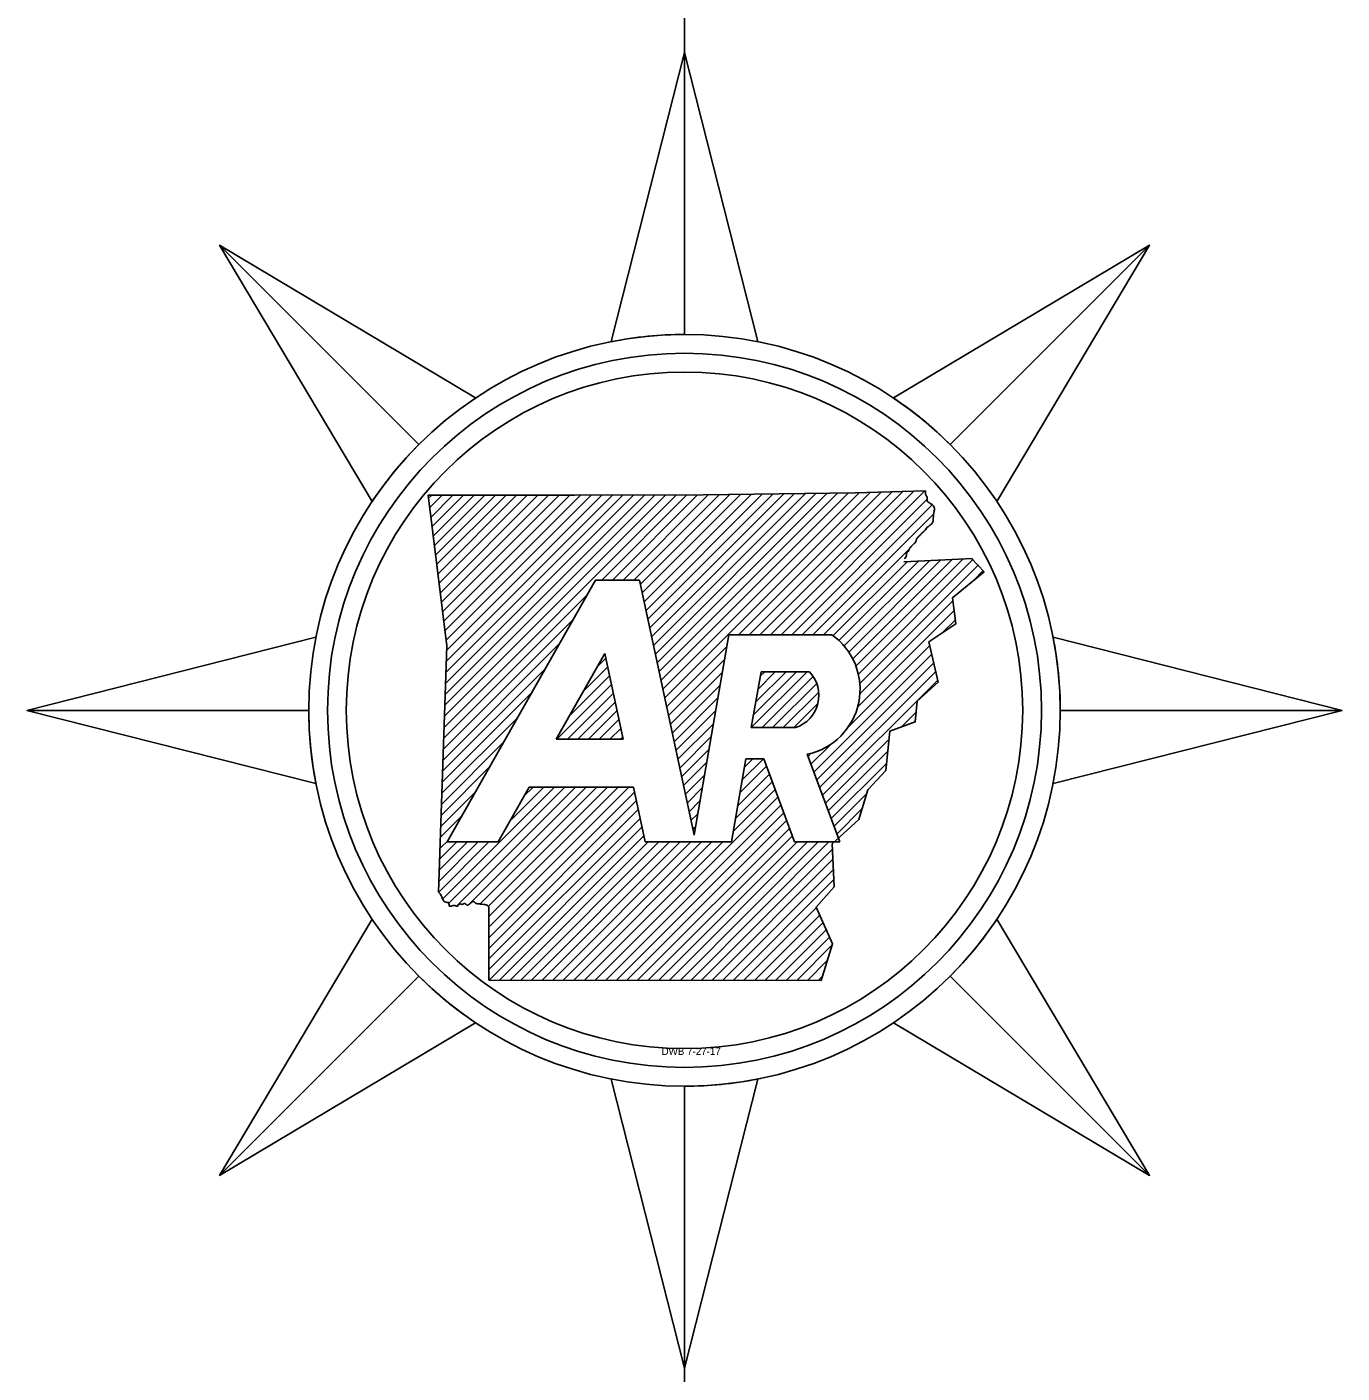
# Model space of a CAD drawing. Extents: x 6028666 to 6031787, y 5366484 to 5368484.
# Drawn here: x 6030749.6 to 6030875, y 5366874.2 to 5367002.5 of the extents above; entities that cross this region are included whole.
import ezdxf

# ---------------------------------------------------------------- set-up
doc = ezdxf.new("R2010")
doc.units = 0
doc.layers.add('R_Draft', color=7, linetype='Continuous')
doc.layers.add('R_Water Annot', color=7, linetype='Continuous')

msp = doc.modelspace()

# ---------------------------------------------------------------- linework, layer by layer
at = {"layer": 'R_Draft'}
for p, q in [((6030812.31, 5367118.56), (6030812.31, 5366977.1)), ((6030812.31, 5367000.07), (6030805.33, 5366972.51)), ((6030812.31, 5366973.19), (6030812.31, 5367000.07)), ((6030767.97, 5366981.7), (6030786.97, 5366962.7)), ((6030786.97, 5366962.7), (6030767.97, 5366981.7)), ((6030767.97, 5366981.7), (6030782.52, 5366957.28)), ((6030856.65, 5366981.7), (6030832.23, 5366967.15)), ((6030837.65, 5366962.7), (6030856.65, 5366981.7)), ((6030837.65, 5366962.7), (6030856.65, 5366981.7)), ((6030789.68, 5366924.81), (6030803.82, 5366949.78)), ((6030803.82, 5366949.78), (6030808.02, 5366949.78)), ((6030816.55, 5366944.57), (6030826.36, 5366944.57)), ((6030875.01, 5366937.36), (6030847.45, 5366944.34)), ((6030800.08, 5366934.61), (6030804.7, 5366942.77)), ((6030819.61, 5366941.04), (6030824.22, 5366941.04)), ((6030749.6, 5366937.36), (6030776.48, 5366937.36)), ((6030776.48, 5366937.36), (6030749.6, 5366937.36)), ((6030749.6, 5366937.36), (6030777.16, 5366930.38)), ((6030848.14, 5366937.36), (6030875.01, 5366937.36)), ((6030848.14, 5366937.36), (6030875.01, 5366937.36)), ((6030818.68, 5366935.71), (6030822.89, 5366935.71)), ((6030800.08, 5366934.61), (6030806.45, 5366934.61)), ((6030819.86, 5366932.75), (6030818.16, 5366932.75)), ((6030822.79, 5366924.81), (6030819.86, 5366932.75)), ((6030824.02, 5366933.17), (6030827.11, 5366924.81)), ((6030797.5, 5366930.05), (6030794.53, 5366924.81)), ((6030807.43, 5366930.05), (6030797.5, 5366930.05)), ((6030794.53, 5366924.81), (6030789.68, 5366924.81)), ((6030816.78, 5366924.81), (6030808.55, 5366924.81)), ((6030827.11, 5366924.81), (6030822.79, 5366924.81)), ((6030856.65, 5366893.02), (6030842.09, 5366917.44)), ((6030767.97, 5366893.02), (6030786.97, 5366912.02)), ((6030786.97, 5366912.02), (6030767.97, 5366893.02)), ((6030837.65, 5366912.02), (6030856.65, 5366893.02)), ((6030837.65, 5366912.02), (6030856.65, 5366893.02)), ((6030767.97, 5366893.02), (6030792.39, 5366907.57)), ((6030812.31, 5366874.65), (6030819.29, 5366902.21)), ((6030812.31, 5366901.53), (6030812.31, 5366901.53)), ((6030812.31, 5366901.53), (6030812.31, 5366786.82)), ((6030812.31, 5366901.53), (6030812.31, 5366874.65))]:
    msp.add_line(p, q, dxfattribs=at)
for points in [[(6030805.33, 5366972.51), (6030812.31, 5367000.07), (6030819.29, 5366972.51)], [(6030782.52, 5366957.28), (6030767.97, 5366981.7), (6030792.39, 5366967.15)], [(6030832.23, 5366967.15), (6030856.65, 5366981.7), (6030842.09, 5366957.28)], [(6030787.85, 5366957.87), (6030801.83, 5366957.86), (6030814.1, 5366957.89), (6030828.57, 5366958.11), (6030835.28, 5366958.27)], [(6030788.86, 5366920.04), (6030789.64, 5366943.5), (6030787.85, 5366957.87)], [(6030839.67, 5366951.85), (6030840.88, 5366950.58), (6030837.87, 5366948.1), (6030838.19, 5366945.6), (6030835.61, 5366943.89), (6030836.49, 5366940.04), (6030834.5, 5366938.22), (6030834.32, 5366936.25), (6030831.89, 5366935.37), (6030831.52, 5366931.64), (6030829.78, 5366929.78), (6030828.93, 5366926.96), (6030826.4, 5366924.64), (6030826.59, 5366920.54), (6030824.86, 5366918.61), (6030826.43, 5366915.1), (6030825.35, 5366911.6)], [(6030833.21, 5366951.52), (6030839.77, 5366951.85)], [(6030808.02, 5366949.78), (6030813.22, 5366925.48), (6030816.55, 5366944.57)], [(6030777.16, 5366930.38), (6030749.6, 5366937.36), (6030777.16, 5366944.34)], [(6030847.45, 5366944.34), (6030875.01, 5366937.36), (6030847.45, 5366930.38)], [(6030804.7, 5366942.77), (6030806.45, 5366934.61)], [(6030818.68, 5366935.71), (6030819.61, 5366941.04)], [(6030818.16, 5366932.75), (6030816.78, 5366924.81)], [(6030808.55, 5366924.81), (6030807.43, 5366930.05)], [(6030825.35, 5366911.6), (6030793.66, 5366911.65), (6030793.64, 5366918.65)], [(6030792.39, 5366907.57), (6030767.97, 5366893.02), (6030782.52, 5366917.44)], [(6030842.09, 5366917.44), (6030856.65, 5366893.02), (6030832.23, 5366907.57)], [(6030819.29, 5366902.21), (6030812.31, 5366874.65), (6030805.33, 5366902.21)]]:
    msp.add_lwpolyline(points, dxfattribs=at)
for radius in [35.83, 32.25]:
    msp.add_circle((6030812.31, 5366937.36), radius, dxfattribs=at)
for centre, radius, start, end in [((6030812.31, 5366937.36), 35.83, 90, 101.2291), ((6030812.31, 5366937.36), 35.83, 45, 56.2291), ((6030812.31, 5366937.36), 35.83, 135, 146.2291), ((6030822.71, 5366939.38), 6.34, 281.8626, 54.8705), ((6030812.31, 5366937.36), 35.83, 0, 11.2291), ((6030821.88, 5366938.79), 3.24, 288.1268, 43.8902), ((6030812.31, 5366937.36), 35.83, 180, 191.2291), ((6030812.31, 5366937.36), 35.83, 315, 326.2291), ((6030812.31, 5366937.36), 35.83, 225, 236.2291), ((6030812.31, 5366937.36), 35.83, 270, 281.2291)]:
    msp.add_arc(centre, radius, start, end, dxfattribs=at)
for points in [[(6030835.28, 5366958.27), (6030835.33, 5366957.89), (6030835.45, 5366957.69), (6030835.46, 5366957.33), (6030835.61, 5366957.17), (6030835.86, 5366957.02), (6030836.09, 5366956.77), (6030836.14, 5366956.47), (6030836.07, 5366956.17), (6030836.05, 5366955.83), (6030836.02, 5366955.54), (6030835.97, 5366955.27), (6030835.76, 5366955.05), (6030835.56, 5366954.9), (6030835.38, 5366954.72), (6030835.25, 5366954.53), (6030835.02, 5366954.32), (6030834.8, 5366954.1), (6030834.62, 5366953.91), (6030834.43, 5366953.67), (6030834.35, 5366953.4), (6030834.15, 5366953.21), (6030833.99, 5366953.04), (6030833.79, 5366952.81), (6030833.68, 5366952.57), (6030833.48, 5366952.3), (6030833.44, 5366952.04), (6030833.31, 5366951.84), (6030833.3, 5366951.8)], [(6030793.64, 5366918.65), (6030793.67, 5366918.63), (6030793.51, 5366918.75), (6030793.28, 5366918.86), (6030793.03, 5366918.87), (6030792.71, 5366918.92), (6030792.45, 5366918.94), (6030792.17, 5366919.13), (6030791.87, 5366918.94), (6030791.55, 5366918.8), (6030791.36, 5366918.95), (6030791.11, 5366918.85), (6030790.93, 5366918.9), (6030790.63, 5366918.69), (6030790.34, 5366918.77), (6030790.14, 5366918.71), (6030789.88, 5366918.72), (6030789.83, 5366919.01), (6030789.57, 5366919.06), (6030789.36, 5366919.18), (6030789.21, 5366919.48), (6030789.11, 5366919.71), (6030788.86, 5366920.04)]]:
    msp.add_spline(points, degree=3, dxfattribs=at)
at = {"layer": 'R_Water Annot'}
for p, q in [((6030821.52, 5366944.57), (6030835.22, 5366958.27)), ((6030787.88, 5366957.56), (6030788.2, 5366957.87)), ((6030788, 5366956.65), (6030789.21, 5366957.87)), ((6030788.11, 5366955.75), (6030790.23, 5366957.87)), ((6030788.22, 5366954.85), (6030791.24, 5366957.87)), ((6030788.33, 5366953.95), (6030792.25, 5366957.87)), ((6030788.45, 5366953.05), (6030793.26, 5366957.87)), ((6030788.56, 5366952.15), (6030794.28, 5366957.87)), ((6030788.67, 5366951.25), (6030795.29, 5366957.87)), ((6030788.78, 5366950.35), (6030796.3, 5366957.87)), ((6030788.89, 5366949.44), (6030797.32, 5366957.87)), ((6030789.01, 5366948.54), (6030798.33, 5366957.87)), ((6030789.12, 5366947.64), (6030799.34, 5366957.86)), ((6030789.23, 5366946.74), (6030800.35, 5366957.86)), ((6030789.34, 5366945.84), (6030801.37, 5366957.86)), ((6030789.38, 5366935.74), (6030811.52, 5366957.88)), ((6030789.41, 5366936.79), (6030810.51, 5366957.88)), ((6030789.45, 5366937.84), (6030809.49, 5366957.88)), ((6030789.46, 5366944.94), (6030802.38, 5366957.86)), ((6030789.48, 5366938.88), (6030808.48, 5366957.88)), ((6030789.52, 5366939.93), (6030807.46, 5366957.88)), ((6030789.55, 5366940.98), (6030806.44, 5366957.87)), ((6030789.57, 5366944.04), (6030803.4, 5366957.87)), ((6030789.59, 5366942.03), (6030805.43, 5366957.87)), ((6030789.62, 5366943.08), (6030804.41, 5366957.87)), ((6030804.43, 5366949.78), (6030812.54, 5366957.89)), ((6030805.44, 5366949.78), (6030813.55, 5366957.89)), ((6030806.45, 5366949.78), (6030814.58, 5366957.9)), ((6030807.47, 5366949.78), (6030815.61, 5366957.91)), ((6030808.1, 5366949.39), (6030816.63, 5366957.93)), ((6030808.28, 5366948.56), (6030817.66, 5366957.94)), ((6030808.46, 5366947.72), (6030818.69, 5366957.96)), ((6030808.64, 5366946.89), (6030819.72, 5366957.98)), ((6030808.81, 5366946.05), (6030820.75, 5366957.99)), ((6030808.99, 5366945.22), (6030821.78, 5366958.01)), ((6030809.17, 5366944.38), (6030822.81, 5366958.02)), ((6030809.35, 5366943.55), (6030823.84, 5366958.04)), ((6030809.53, 5366942.71), (6030824.87, 5366958.06)), ((6030809.71, 5366941.88), (6030825.9, 5366958.07)), ((6030809.89, 5366941.05), (6030826.93, 5366958.09)), ((6030810.06, 5366940.21), (6030827.96, 5366958.1)), ((6030810.24, 5366939.38), (6030828.99, 5366958.12)), ((6030810.42, 5366938.54), (6030830.03, 5366958.15)), ((6030817.46, 5366944.57), (6030831.07, 5366958.17)), ((6030818.48, 5366944.57), (6030832.1, 5366958.2)), ((6030819.49, 5366944.57), (6030833.14, 5366958.22)), ((6030820.5, 5366944.57), (6030834.18, 5366958.24)), ((6030822.53, 5366944.57), (6030835.44, 5366957.48)), ((6030823.54, 5366944.57), (6030835.93, 5366956.96)), ((6030824.56, 5366944.57), (6030836.06, 5366956.07)), ((6030825.57, 5366944.57), (6030833.75, 5366952.75)), ((6030826.49, 5366944.48), (6030833.55, 5366951.53)), ((6030827.04, 5366944.01), (6030834.62, 5366951.59)), ((6030827.54, 5366943.5), (6030835.69, 5366951.64)), ((6030827.98, 5366942.92), (6030836.76, 5366951.7)), ((6030828.35, 5366942.28), (6030837.82, 5366951.75)), ((6030828.66, 5366941.58), (6030838.89, 5366951.81)), ((6030828.9, 5366940.8), (6030839.85, 5366951.76)), ((6030829.03, 5366939.92), (6030840.33, 5366951.22)), ((6030839.88, 5366949.75), (6030840.8, 5366950.68)), ((6030789.34, 5366934.69), (6030803.02, 5366948.37)), ((6030828.83, 5366937.69), (6030838.03, 5366946.89)), ((6030829.04, 5366938.92), (6030837.91, 5366947.79)), ((6030789.31, 5366933.64), (6030801.7, 5366946.03)), ((6030836.89, 5366944.74), (6030838.14, 5366945.99)), ((6030789.27, 5366932.59), (6030800.37, 5366943.69)), ((6030810.6, 5366937.71), (6030816.35, 5366943.46)), ((6030827.95, 5366935.79), (6030835.69, 5366943.54)), ((6030803.98, 5366941.5), (6030804.8, 5366942.32)), ((6030810.78, 5366936.87), (6030816.14, 5366942.23)), ((6030824.64, 5366931.48), (6030835.88, 5366942.71)), ((6030824.92, 5366930.74), (6030836.07, 5366941.89)), ((6030789.24, 5366931.55), (6030799.05, 5366941.36)), ((6030801.34, 5366936.83), (6030805.16, 5366940.65)), ((6030802.66, 5366939.17), (6030804.98, 5366941.49)), ((6030810.96, 5366936.04), (6030815.92, 5366941)), ((6030818.68, 5366935.71), (6030824.01, 5366941.04)), ((6030818.89, 5366936.93), (6030823, 5366941.04)), ((6030819.1, 5366938.16), (6030821.99, 5366941.04)), ((6030819.32, 5366939.39), (6030820.97, 5366941.04)), ((6030819.53, 5366940.61), (6030819.96, 5366941.04)), ((6030819.7, 5366935.71), (6030824.58, 5366940.59)), ((6030825.19, 5366930), (6030836.26, 5366941.07)), ((6030789.2, 5366930.5), (6030797.73, 5366939.02)), ((6030800.13, 5366934.61), (6030805.34, 5366939.82)), ((6030811.14, 5366935.2), (6030815.71, 5366939.77)), ((6030820.71, 5366935.71), (6030824.92, 5366939.92)), ((6030821.72, 5366935.71), (6030825.11, 5366939.1)), ((6030825.46, 5366929.26), (6030836.45, 5366940.24)), ((6030801.14, 5366934.61), (6030805.51, 5366938.98)), ((6030802.15, 5366934.61), (6030805.69, 5366938.15)), ((6030811.32, 5366934.37), (6030815.5, 5366938.55)), ((6030822.74, 5366935.71), (6030825.02, 5366938)), ((6030789.17, 5366929.45), (6030796.4, 5366936.68)), ((6030803.17, 5366934.61), (6030805.87, 5366937.31)), ((6030804.18, 5366934.61), (6030806.05, 5366936.48)), ((6030811.49, 5366933.53), (6030815.28, 5366937.32)), ((6030832.98, 5366935.76), (6030834.4, 5366937.19)), ((6030805.2, 5366934.61), (6030806.23, 5366935.64)), ((6030811.67, 5366932.7), (6030815.07, 5366936.09)), ((6030789.13, 5366928.4), (6030795.08, 5366934.35)), ((6030806.21, 5366934.61), (6030806.41, 5366934.81)), ((6030811.85, 5366931.86), (6030814.85, 5366934.87)), ((6030824.37, 5366932.22), (6030826.3, 5366934.15)), ((6030825.74, 5366928.52), (6030831.82, 5366934.6)), ((6030812.03, 5366931.03), (6030814.64, 5366933.64)), ((6030817.81, 5366930.72), (6030819.83, 5366932.75)), ((6030818.02, 5366931.95), (6030818.82, 5366932.75)), ((6030824.1, 5366932.96), (6030824.4, 5366933.27)), ((6030826.01, 5366927.78), (6030831.7, 5366933.47)), ((6030789.1, 5366927.35), (6030793.76, 5366932.01)), ((6030812.21, 5366930.19), (6030814.43, 5366932.41)), ((6030817.59, 5366929.5), (6030820.13, 5366932.03)), ((6030826.28, 5366927.04), (6030831.59, 5366932.34)), ((6030789.25, 5366919.4), (6030799.9, 5366930.05)), ((6030789.85, 5366918.98), (6030800.91, 5366930.05)), ((6030790.58, 5366918.7), (6030801.93, 5366930.05)), ((6030791.78, 5366918.89), (6030802.94, 5366930.05)), ((6030792.81, 5366918.9), (6030803.96, 5366930.05)), ((6030793.61, 5366918.69), (6030804.97, 5366930.05)), ((6030793.64, 5366916.69), (6030807, 5366930.05)), ((6030793.64, 5366917.71), (6030805.98, 5366930.05)), ((6030795.68, 5366926.84), (6030798.89, 5366930.05)), ((6030797, 5366929.17), (6030797.87, 5366930.05)), ((6030812.39, 5366929.36), (6030814.21, 5366931.18)), ((6030817.16, 5366927.04), (6030820.67, 5366930.55)), ((6030817.38, 5366928.27), (6030820.4, 5366931.29)), ((6030789.06, 5366926.3), (6030792.43, 5366929.67)), ((6030793.65, 5366915.68), (6030807.53, 5366929.57)), ((6030803.79, 5366911.64), (6030821.22, 5366929.07)), ((6030812.57, 5366928.52), (6030814, 5366929.96)), ((6030816.95, 5366925.81), (6030820.95, 5366929.81)), ((6030826.56, 5366926.3), (6030829.66, 5366929.41)), ((6030793.65, 5366914.67), (6030807.71, 5366928.73)), ((6030793.65, 5366913.66), (6030807.89, 5366927.9)), ((6030804.8, 5366911.64), (6030821.49, 5366928.33)), ((6030805.81, 5366911.63), (6030821.77, 5366927.59)), ((6030812.74, 5366927.69), (6030813.78, 5366928.73)), ((6030812.92, 5366926.85), (6030813.57, 5366927.5)), ((6030826.83, 5366925.56), (6030829.23, 5366927.96)), ((6030789.03, 5366925.26), (6030791.11, 5366927.34)), ((6030793.65, 5366912.65), (6030808.07, 5366927.06)), ((6030793.67, 5366911.65), (6030808.24, 5366926.23)), ((6030806.82, 5366911.63), (6030822.04, 5366926.85)), ((6030813.1, 5366926.02), (6030813.36, 5366926.27)), ((6030789, 5366924.21), (6030789.79, 5366925)), ((6030794.68, 5366911.65), (6030808.42, 5366925.39)), ((6030807.84, 5366911.63), (6030822.31, 5366926.11)), ((6030808.85, 5366911.63), (6030822.59, 5366925.37)), ((6030788.87, 5366920.03), (6030793.65, 5366924.81)), ((6030788.89, 5366921.06), (6030792.64, 5366924.81)), ((6030788.93, 5366922.11), (6030791.62, 5366924.81)), ((6030788.96, 5366923.16), (6030790.61, 5366924.81)), ((6030795.69, 5366911.65), (6030808.85, 5366924.81)), ((6030796.71, 5366911.65), (6030809.86, 5366924.81)), ((6030797.72, 5366911.65), (6030810.88, 5366924.81)), ((6030798.73, 5366911.65), (6030811.89, 5366924.81)), ((6030799.74, 5366911.64), (6030812.91, 5366924.81)), ((6030800.75, 5366911.64), (6030813.92, 5366924.81)), ((6030801.77, 5366911.64), (6030814.93, 5366924.81)), ((6030802.78, 5366911.64), (6030815.95, 5366924.81)), ((6030809.86, 5366911.63), (6030823.04, 5366924.81)), ((6030810.87, 5366911.63), (6030824.05, 5366924.81)), ((6030811.88, 5366911.62), (6030825.07, 5366924.81)), ((6030812.9, 5366911.62), (6030826.08, 5366924.81)), ((6030813.91, 5366911.62), (6030826.42, 5366924.13)), ((6030814.92, 5366911.62), (6030826.46, 5366923.17)), ((6030815.93, 5366911.62), (6030826.51, 5366922.2)), ((6030816.94, 5366911.62), (6030826.56, 5366921.23)), ((6030817.95, 5366911.61), (6030824.89, 5366918.55)), ((6030818.97, 5366911.61), (6030825.2, 5366917.85)), ((6030819.98, 5366911.61), (6030825.52, 5366917.15)), ((6030820.99, 5366911.61), (6030825.83, 5366916.45)), ((6030822, 5366911.61), (6030826.14, 5366915.75)), ((6030823.01, 5366911.61), (6030826.4, 5366915)), ((6030824.03, 5366911.6), (6030825.95, 5366913.53)), ((6030825.04, 5366911.6), (6030825.49, 5366912.05))]:
    msp.add_line(p, q, dxfattribs=at)
msp.add_circle((6030812.31, 5366937.36), 34.04, dxfattribs=at)

# ---------------------------------------------------------------- texts
at = {"layer": 'R_Draft'}
msp.add_text('DWB 7-27-17', height=0.6967, dxfattribs=at).set_placement((6030810.12, 5366904.51))

doc.saveas('drawing.dxf')
